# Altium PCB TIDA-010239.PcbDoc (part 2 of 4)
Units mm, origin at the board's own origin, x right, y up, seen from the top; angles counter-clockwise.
Board outline 160 x 175 mm, 4 copper layers (Top Layer, Inside 1, Inside 2, Bottom Layer), stack 1.787 mm thick; 299 components, 146 nets, 710 pads, 164 vias.
Unrouted connection lines stored in the file: 9.
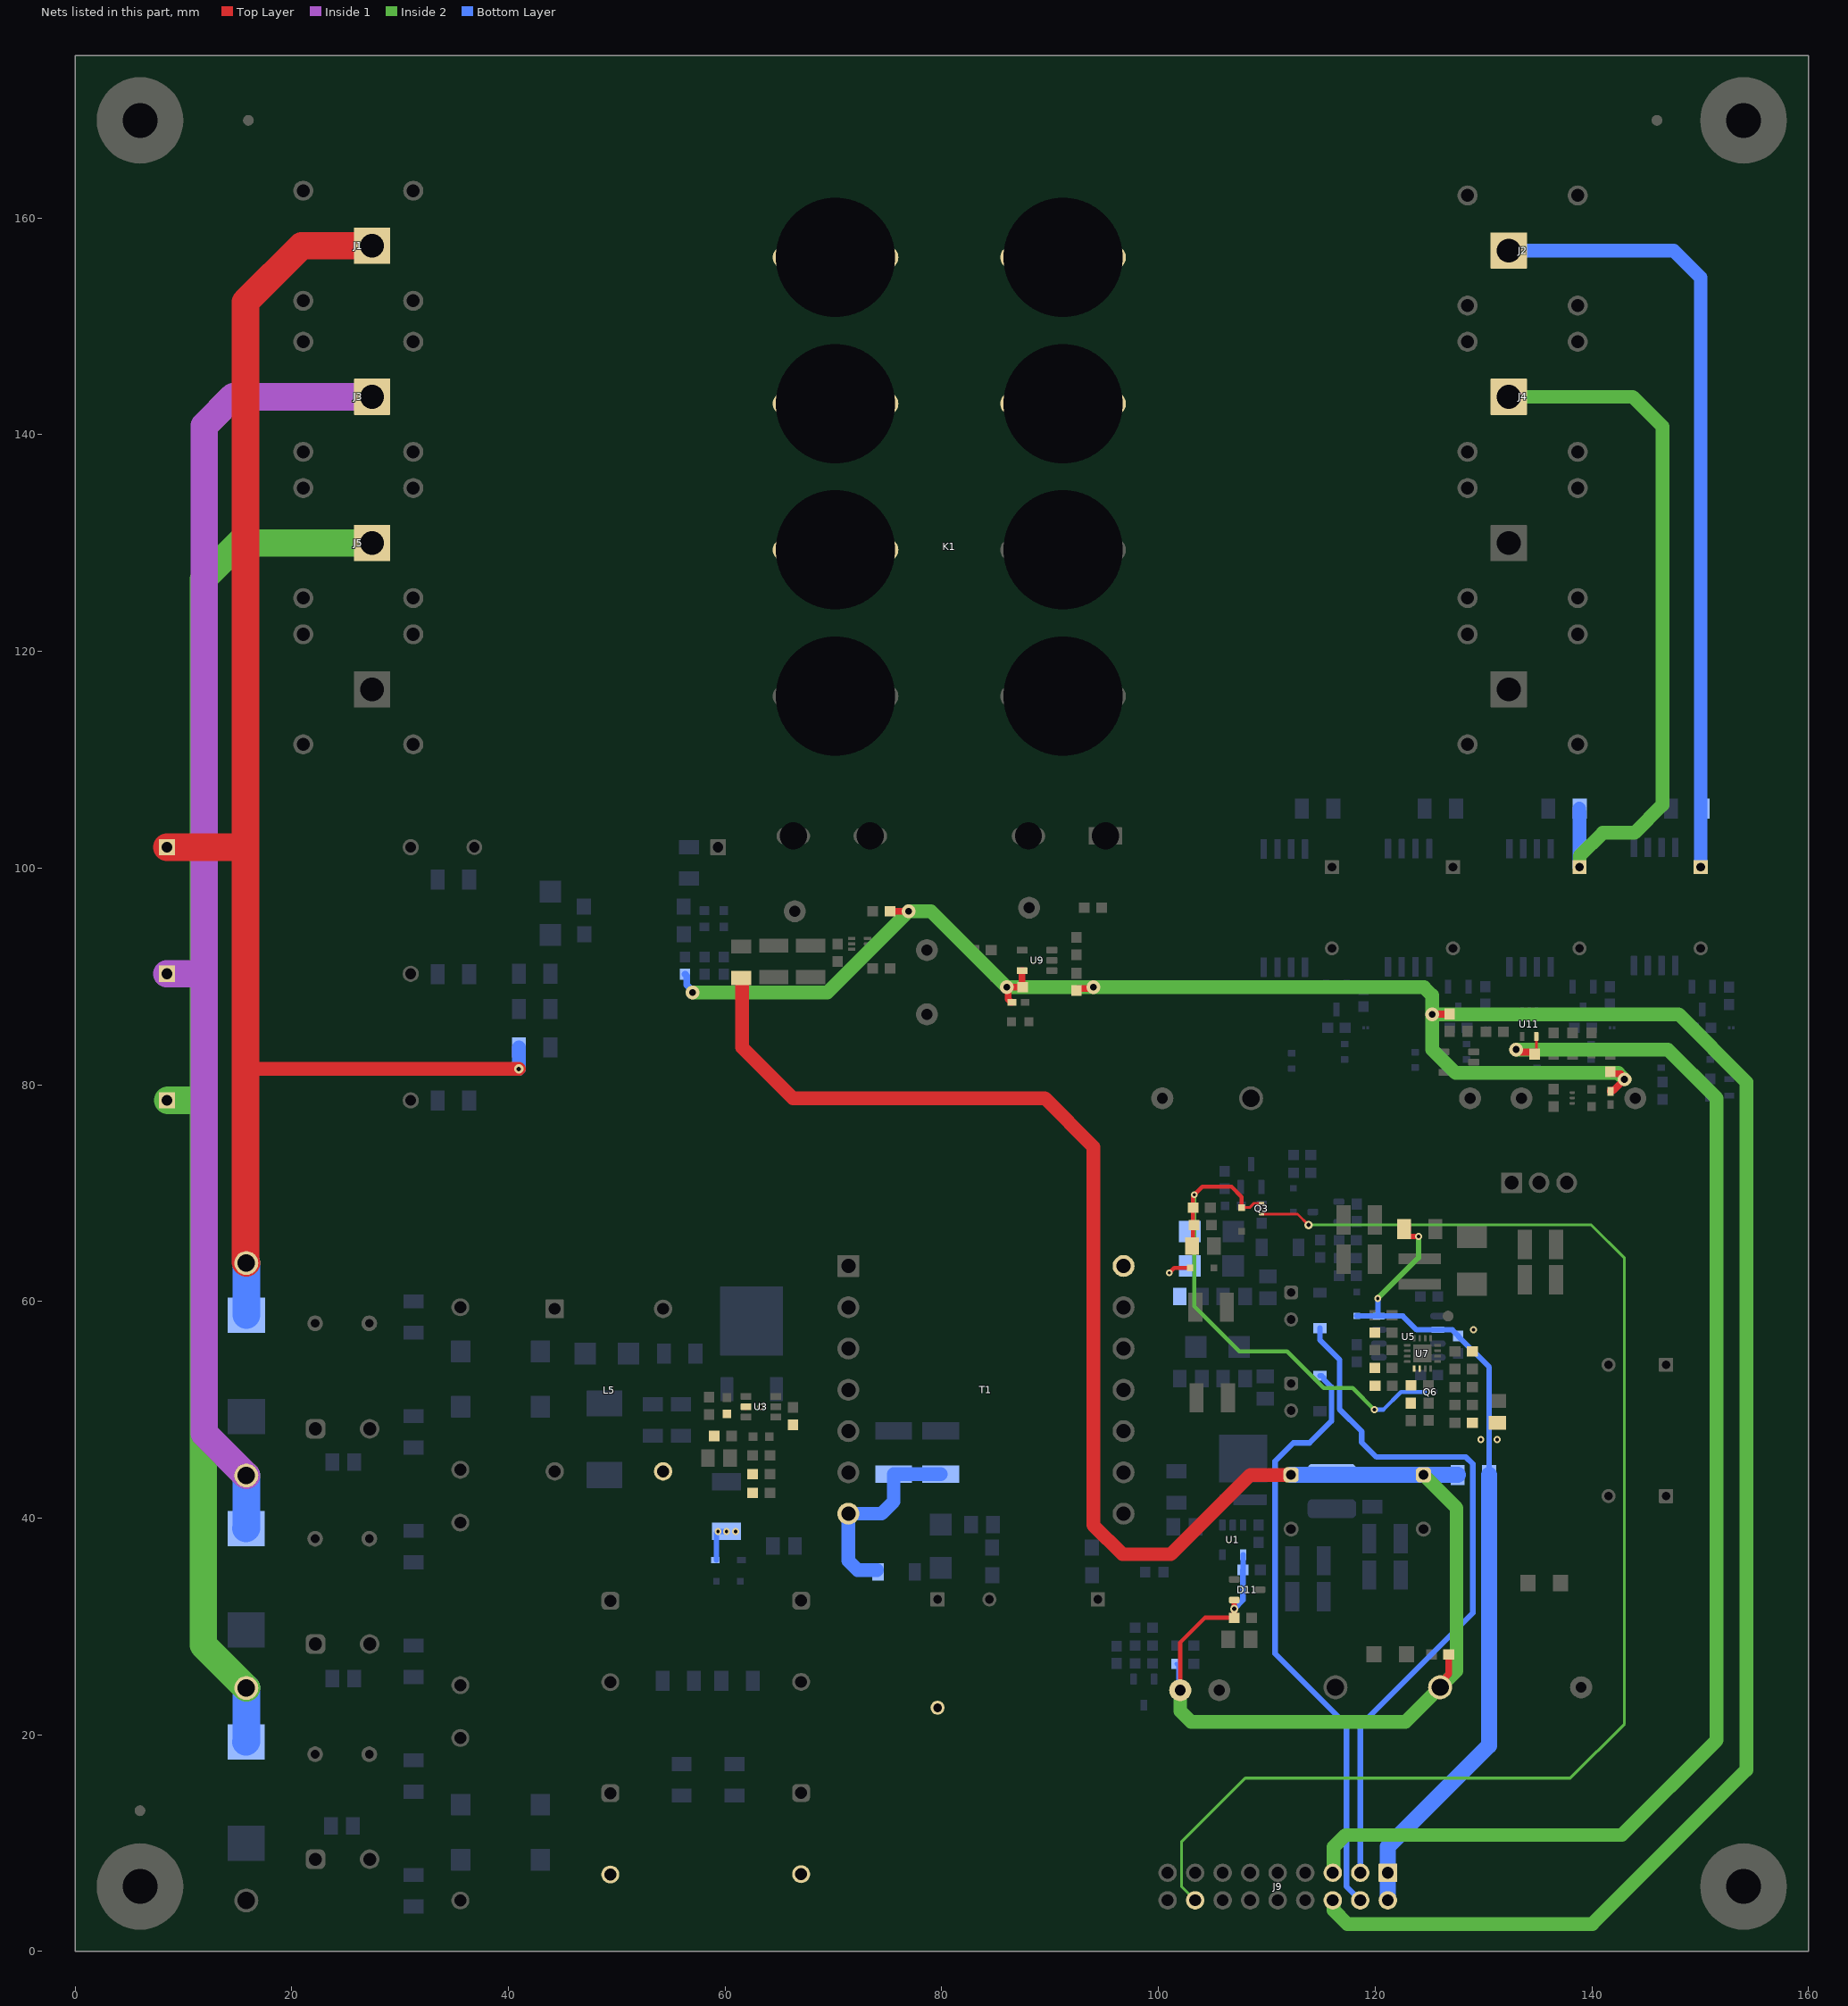
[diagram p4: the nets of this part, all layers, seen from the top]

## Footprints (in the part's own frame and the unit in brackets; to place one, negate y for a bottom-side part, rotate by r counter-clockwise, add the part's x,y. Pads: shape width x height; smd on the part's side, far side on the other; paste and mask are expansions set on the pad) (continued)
WCAP-ATUL_D10H20 [mm] "Aluminum Electrolytic Capacitors, 10x20mm"
  rrect50% 1.4x1.4 hole 0.9: 1(2.5,0)
  round 1.4 hole 0.9: 2(-2.5,0)
  silkscreen extent -5.25,-5.25 5.25,5.25, body extent -4.99,-5 5,5, height 20.31
WCAP-CSGP_0603_L1.6W0.8H0.8_Reflow [mm] "Ceramic Capacitors, body 1.6x0.8mm"
  rect 0.8x0.8 smd: 1(-0.75,0) 2(0.75,0)
  body extent -0.8,-0.4 0.8,0.4, height 0.8
WCAP-FTBE_L18W8.5H15 [mm] "THT Film Capacitors, body 18x8.5mm"
  round 1.65 hole 1.1: 1(-7.5,0) 2(7.5,0)
  silkscreen extent -9.75,-4.75 9.75,4.75, body extent -9,-4.25 9,4.25, height 15.05
WE-PD2-S [mm] "WURTH"
  rrect50% 1.75x4.5 smd: 1(-1.625,0) 2(1.625,0)
  Top Layer region: -1.375,2.25 -0.75,2.25 -0.75,-2.25 -1.375,-2.25
  Top Layer region: 1.375,-2.25 0.75,-2.25 0.75,2.25 1.375,2.25
  silkscreen extent -0.4,-2.1 0.4,2.12, body extent -2.24,-2 2.24,2, height 3.18
WE-TI_1014 [mm] "Radial Leaded Wire Wound Inductor, body diameter 10.5mm"
  rrect50% 1.8x1.8 hole 1.2: 1(-2.5,0)
  round 1.8 hole 1.2: 2(2.5,0)
  silkscreen extent -5.87,-5.25 5.25,5.25, body extent -5,-5 5,5, height 14.1
WEEE_Minimum [mm] "WEEElie bin"
  silkscreen extent -2.42,-4.38 2.52,2.65
WL-SMCW_GREEN [mm] "WURTH"
  rect 0.8x0.8 smd: 1(-0.8,0) 2(0.8,0)
  silkscreen extent -1.9,-0.8 1.2,0.8, body extent -0.85,-0.45 0.85,0.45, height 0.8
WL_SMCW_RED_1206 [mm] "SMD, 2-Leads, Body 3.2x1.6mm, Pitch 3mm"
  rect 1.4x1.5 smd: 1(-1.5,0) 2(1.5,0)
  silkscreen extent -2.9,-1.1 2.2,1.1, body extent -1.6,-0.85 1.6,0.85, height 0.78
X3-DFN0603-2 [mm] "SMD, 2-Leads, Body 0.62x0.32mm"
  rect 0.23x0.3 smd mask+0.102: 1(-0.19,0) 2(0.19,0)
  silkscreen extent -0.69,-0.48 0.32,0.48, body extent -0.32,-0.17 0.32,0.17, height 0.35
XEL4030_310 [mm] "SMD, 2-Leads, Body 4x4mm, Pitch 2.37mm"
  rect 0.98x3.9 smd: 1(-1.185,0) 2(1.185,0)
  silkscreen extent -2.3,-2.3 2.3,2.3, body extent -2.15,-2.15 2.15,2.15, height 3.1
YJK0003A#1 [mm] "SMD, 3-Leads, Body 1.49x0.73mm"
  rrect50% 0.2x0.39 on Top Paste: 1(-0.525,0) 2(0,0) 3(0.525,0)
  rrect80% 0.25x0.49 smd paste-0.15 mask-0.05: 1(-0.5,0) 2(0,0) 3(0.5,0)
  silkscreen extent -0.9,-0.5 0.9,0.5, body extent -0.75,-0.37 0.74,0.36, height 0.35
YJK0003A#2 [mm] "SMD, 3-Leads, Body 1.49x0.73mm"
  rrect50% 0.2x0.39 on Bottom Paste: 1(-0.525,0) 2(0,0) 3(0.525,0)
  rrect80% 0.25x0.49 smd paste-0.15 mask-0.05: 1(-0.5,0) 2(0,0) 3(0.5,0)
  silkscreen extent -0.9,-0.5 0.9,0.5, body extent -0.75,-0.37 0.74,0.36, height 0.35

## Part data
C1 C11: library part CMP-0008246-2, "CAP, CERM, 68 pF, 250 V, +/- 5%, C0G/NP0, 0805", Cap_Case=0805, Manufacturer=MuRata, Supplier Part Number 1=490-5540-1-ND, TempCo=C0G/NP0, Tolerance_%=5%, Value1=Unknown, Value2=250V, ValueDisplayed=68pF
C2 C3: library part CMP-0127096-1, "Cap Ceramic Disc 3300pF 20% 300VAC Thru-Hole 10.0x5.0x10.0 Ammo pack", Manufacturer=Murata, Operating Temperature Range="-40°C to +125°C", TempCo=+20/-55%, Temperature Characteristic=E, Tolerance_%=20%, ValueDisplayed=3300pF, Voltage Ac Rating X=440V, Voltage Ac Rating Y=300V
C4 C12: library part CMP-0116473-1, "WCAP-ATG8 Aluminum Electrolytic Capacitor, Radial, THT, D6.3 x H11mm, 100uF, 25V", Capacitance Tolerance=+/-20%, Leakage Current=25uA, Manufacturer="Wurth Elektronik", Operating Temperature Max=85°C, Operating Temperature Min=-40°C, Rated Voltage (DC)=25V, Ripple Current=209mA
C5 C10 C21 C22 C23 C24 C45 C46 C48 C49 C58 C59: library part CMP-0082267-1, "CAP, CERM, 22 µF, 25 V,+/- 10%, X7R, 1210", Cap_Case=1210, Manufacturer=Yageo, Supplier Part Number 1=311-2032-2-ND, TempCo=X7R, Tolerance_%=10%, Value1="0.001 ohm", Value2=25V, ValueDisplayed=22µF
C6 C7: library part CMP-0009326-2, "CAP, CERM, 0.1 uF, 1000 V, +/- 10%, X7R, 1812", Cap_Case=1812, Manufacturer=Kemet, Supplier Part Number 1=399-6523-1-ND, TempCo=X7R, Tolerance_%=10%, Value1=Unknown, Value2=1000V, ValueDisplayed=0.1uF
C8: library part CMP-0009039-2, "CAP, CERM, 1000 pF, 500 V, +/- 10%, X7R, 1206", Cap_Case=1206, Manufacturer=Vishay-Vitramon, Supplier Part Number 1=720-1019-1-ND, TempCo=X7R, Tolerance_%=10%, Value1=Unknown, Value2=500V, ValueDisplayed=1000pF
C9 C15 C20: library part CMP-0105615-1, "WCAP-FTBE Film Capacitor, THT, L18 x W8.5 x H15mm, 100nF, 1000V", Capacitance Tolerance=+/-10%, Insulation Resistance=9000MOhm, Manufacturer="Wurth Elektronik", Operating Temperature Max=85°C, Operating Temperature Min=-40°C, Rate of Voltage Rise=44V/us, Rated Voltage (DC)=1000V
C13 C14 C16 C17: library part CMP-0102466-1, "WCAP-ATG5 Aluminum Electrolytic Capacitor, Radial, THT, D16 x H25mm, 68µF, 400V", Capacitance Tolerance=+/-20%, Leakage Current=816uA, Manufacturer="Wurth Elektronik", Operating Temperature Max=105°C, Operating Temperature Min=-25°C, Rated Voltage (DC)=400V, Ripple Current=410mA
C18 C29 C32 C39 C41 C43 C44 C47 C52 C60 C61 C64 C67 C73: library part CMP-0007044-5, "CAP, CERM, 0.1 uF, 50 V, +/- 10%, X7R, 0603", Cap_Case=0603, Manufacturer=TDK, Supplier Part Number 1=445-1314-1-ND, TempCo=X7R, Tolerance_%=10%, Value1="0.0296 ohm", Value2=50V, ValueDisplayed=0.1uF
C19: library part CMP-0007499-4, "CAP, CERM, 2.2 uF, 16 V, +/- 10%, X7R, 0603", Cap_Case=0603, Manufacturer=MuRata, Supplier Part Number 1=81-GRM188Z71C225KE3D, TempCo=X7R, Tolerance_%=10%, Value1=Unknown, Value2=16V, ValueDisplayed=2.2uF
C25 C26: library part CMP-0116844-1, "WCAP-ATUL Aluminum Electrolytic Capacitor, Radial, THT, D10 x H20mm, 680µF, 25V", Capacitance Tolerance=20%, Leakage Current=170uA, Manufacturer="Wurth Elektronik", Operating Temperature Max=105°C, Operating Temperature Min=-40°C, Rated Voltage (DC)=25V, Ripple Current=1400mA
C27: library part CMP-0008236-2, "CAP, CERM, 100 pF, 250 V, +/- 5%, C0G/NP0, 0805", Cap_Case=0805, Manufacturer=MuRata, Supplier Part Number 1=490-5542-1-ND, TempCo=C0G/NP0, Tolerance_%=5%, Value1=Unknown, Value2=250V, ValueDisplayed=100pF
C28: library part CMP-0006897-4, "CAP, CERM, 2200 pF, 50 V, +/- 10%, X7R, 0603", Cap_Case=0603, Manufacturer=Kemet, Supplier Part Number 1=1362428, TempCo=X7R, Tolerance_%=10%, Value1=Unknown, Value2=50V, ValueDisplayed=2200pF
C30 C37: library part CMP-0008802-2, "CAP, CERM, 10 uF, 50 V, +/- 10%, X7R, 1206", Cap_Case=1206, Manufacturer=Samsung, Supplier Part Number 1=1276-6767-1-ND, TempCo=X7R, Tolerance_%=10%, Value1=Unknown, Value2=50V, ValueDisplayed=10uF
C31: library part CMP-0007870-2, "CAP, CERM, 4.7 uF, 25 V, +/- 10%, X7R, 0805", Cap_Case=0805, Manufacturer=TDK, Supplier Part Number 1=445-5972-1-ND, TempCo=X7R, Tolerance_%=10%, Value1=Unknown, Value2=25V, ValueDisplayed=4.7uF
C33 C38: library part CMP-0118889-1, "WCAP-CSGP Multilayer Ceramic Chip Capacitor, General Purpose, size 0603, NP0, 100pF, 50VDC", Capacitance Tolerance=+/-5%, Insulation Resistance=10GOhm, Manufacturer="Wurth Elektronik", Operating Temperature Max=125°C, Operating Temperature Min=-55°C, Rated Voltage (DC)=50V
C34: library part CMP-0115476-1, "WCAP-CSGP Multilayer Ceramic Chip Capacitor, General Purpose, size 0603, X7R, 47nF, 50VDC", Capacitance Tolerance=+/-10%, Insulation Resistance=10GOhm, Manufacturer="Wurth Elektronik", Operating Temperature Max=125°C, Operating Temperature Min=-55°C, Rated Voltage (DC)=50V
C35: library part CMP-0006893-4, "CAP, CERM, 220 pF, 50 V, +/- 5%, C0G/NP0, 0603", Cap_Case=0603, Manufacturer=Kemet, Supplier Part Number 1=399-1066-1-ND, TempCo=C0G/NP0, Tolerance_%=5%, Value1=Unknown, Value2=50V, ValueDisplayed=220pF
C36: library part CMP-0006835-4, "CAP, CERM, 4700 pF, 50 V, +/- 10%, X7R, 0603", Cap_Case=0603, Manufacturer="Wurth Elektronik", Supplier Part Number 1=710-885012206087, TempCo=X7R, Tolerance_%=10%, Value1=Unknown, Value2=50V, ValueDisplayed=4700pF
C40 C42: library part CMP-0095175-1, "2.5 F (EDLC) Supercapacitor 3.9 V Radial 80mOhm 5000 Hrs @ 85°C", Digikey Part Number=283-PHVL-3R9V255-R-ND, Manufacturer="Cooper Bussmann", Mouser Part Number=504-PHVL-3R9V255-R, Operating Temperature Range="-40°C to +85°C", Tolerance_%=30%, ValueDisplayed=2.5F
C50: library part CMP-0084374-1, "CAP, CERM, 6.8 pF, 100 V,+/- 3.7%, C0G/NP0, 0603", Cap_Case=0603, Manufacturer=Yageo, TempCo=C0G/NP0, Tolerance_%=3.7%, Value2=100V, ValueDisplayed=6.8pF
C51: library part CMP-0006834-5, "CAP, CERM, 470 pF, 50 V, +/- 10%, X7R, 0603", Cap_Case=0603, Manufacturer="Wurth Elektronik", Supplier Part Number 1=710-885012206081, TempCo=X7R, Tolerance_%=10%, Value1=Unknown, Value2=50V, ValueDisplayed=470pF
C53: library part CMP-0006854-4, "CAP, CERM, 0.01 uF, 50 V, +/- 10%, X7R, 0603", Cap_Case=0603, Manufacturer=Kemet, Supplier Part Number 1=399-1091-1-ND, TempCo=X7R, Tolerance_%=10%, Value1=Unknown, Value2=50V, ValueDisplayed=0.01uF
C54 C55 C56: library part CMP-0012419-3, "CAP, Film, 1 uF, 630 V, +/- 20%, 0.018 ohm, TH", Manufacturer=TDK, Supplier Part Number 1=495-2324-ND, Tolerance_%=20%, Value1="0.018 ohm", Value2=630V, ValueDisplayed=1uF
C57: library part CMP-0040174-1, "Cap Film Suppression Y2 0.1uF 1250VDC/300VAC PP 20% (26 X 10.5 X 19mm) Radial 22.5mm 110C Tray", Digikey Part Number=399-5422-ND, Manufacturer=Kemet, Mouser Part Number=80-PHE850ED6100MD18, Operating Temperature Range="-55°C to +110°C", Tolerance_%=20%, ValueDisplayed=0.1uF, Voltage Ac Rating Y=300V
C62 C65 C69 C71: library part CMP-0120129-1, "1000 pF ±20% 440VAC Ceramic Capacitor Y5U (E) Radial, Disc", Digikey Part Number=BC5267CT-ND, Manufacturer=Vishay, Mouser Part Number=72-VY2102M29Y5US6TV7, Operating Temperature Range="-40°C to +125°C", TempCo=+22/-56%, Temperature Characteristic=Y5U, Tolerance_%=20%, ValueDisplayed=1000pF, Voltage Ac Rating X=440V, Voltage Ac Rating Y=300V
C63 C68 C70 C72: library part CMP-0085572-1, "CAP, CERM, 47 pF, 100 V,+/- 5%, C0G/NP0, AEC-Q200 Grade 1, 0603", Cap_Case=0603, Manufacturer=Kemet, TempCo=C0G/NP0, Tolerance_%=5%, Value2=100V, ValueDisplayed=47pF
C66: library part CMP-0006751-4, "CAP, CERM, 100 pF, 25 V, +/- 10%, X7R, 0603", Cap_Case=0603, Manufacturer=AVX, Supplier Part Number 1=55J3899, TempCo=X7R, Tolerance_%=10%, Value1=Unknown, Value2=25V, ValueDisplayed=100pF
C74: library part CMP-0007139-4, "CAP, CERM, 1 uF, 25 V, +/- 10%, X7R, AEC-Q200 Grade 1, 0603", Cap_Case=0603, Manufacturer=MuRata, Supplier Part Number 1=490-10673-1-ND, TempCo=X7R, Tolerance_%=10%, Value1=Unknown, Value2=25V, ValueDisplayed=1uF
C75: library part CMP-0008918-2, "CAP, CERM, 2200 pF, 1000 V, +/- 10%, X7R, 1206", Cap_Case=1206, Manufacturer=MuRata, Supplier Part Number 1=490-3496-1-ND, TempCo=X7R, Tolerance_%=10%, Value1=Unknown, Value2=1000V, ValueDisplayed=2200pF
C76: library part CMP-0108297-1, "WCAP-CSGP Multilayer Ceramic Chip Capacitor, General Purpose, size 0603, X7R, 1nF, 50VDC", Capacitance Tolerance=+/-10%, Insulation Resistance=10GOhm, Manufacturer="Wurth Elektronik", Operating Temperature Max=125°C, Operating Temperature Min=-55°C, Rated Voltage (DC)=50V
C77: library part CMP-0091480-1, "0603 0.22 uF 16 V ±10 % Tolerance X7R SMT Multilayer Ceramic Capacitor", Digikey Part Number=311-1426-1-ND, Manufacturer=Yageo, Mouser Part Number=603-CC603KRX7R7BB224, Operating Temperature Range="-55°C to +125°C", TempCo=15%, Temperature Characteristic=X7R, Tolerance_%=10%, ValueDisplayed=220nF, Voltage=16V
D1 D5 D16: library part CMP-0028981-2, "Diode, Schottky, 200 V, 1 A, SMA", Manufacturer="Micro Commercial Components", Value1=1A, Value2=0.92V
D2 D6: library part CMP-0028526-2, "Diode, Schottky, 40 V, 0.5 A, SOD-123", Manufacturer="ON Semiconductor", Value1=0.5A, Value2=0.51V
D3 D8: library part CMP-0029252-3, "Diode, Switching-Bridge, 1000 V, 2.2 A, 8.25x6.6mm", Manufacturer="Micro Commercial Components", Value1=2.2A, Value2=1.1V
D4: library part CMP-0127069-1, "209V Clamp 7.2A Ipp Tvs Diode Surface Mount DO-214AB (SMCJ)", Breakdown Voltage=144V, Clamping Voltage=209V, Digikey Part Number=SMCJ130ALFCT-ND, Manufacturer="Littelfuse Inc", Mouser Part Number=576-SMCJ130A, Operating Temperature Range="-65°C to +150°C"
D7 D35: library part CMP-0076882-2, "Diode, Ultrafast, 1000 V, 1 A, SMA", Manufacturer="Diodes Inc.", Value1=1A, Value2=1.7V
D9 D19: library part CMP-0002935-3, "LED, Red, SMD", Color=Red, Manufacturer="Wurth Elektronik", Power_TotalModule=72mW, Value1=0.072W, Value2=2V
D10: library part CMP-0077026-2, "Diode, Ultrafast, 400 V, 1 A, SMA", Manufacturer="Diodes Inc.", Value1=1A, Value2=1.3V
D11: library part CMP-0028613-2, "Diode, Schottky, 30 V, 0.2 A, SOT-23", Manufacturer="ON Semiconductor", Value1=0.2A, Value2=0.8V
D12 D14 D17 D18: library part CMP-0029150-2, "Diode, Switching, 200 V, 0.2 A, AEC-Q101, SOD-323", Manufacturer="ON Semiconductor", Value1=0.2A, Value2=1.25V
D13: library part CMP-0124335-1, "Diode Zener Single 43V ±5% 200mW 2-Pin SOD-323 T/R", Digikey Part Number=112-BZX384C43-E3-08CT-ND, Manufacturer=Vishay, Max Reverse Leakage Current=0.05uA, Mouser Part Number=78-BZX384C43-E3-08, Operating Temperature Range="-55°C to +150°C", Power_W=200mW
D15: library part CMP-0085763-1, "Diode, Zener, 16 V, 300 mW, AEC-Q101, SOD-323", Manufacturer="ON Semiconductor", Power_W=300mW, Value1=0.3W
D20: library part CMP-0028529-2, "Diode, Schottky, 40 V, 2 A, SMB", Manufacturer="ON Semiconductor", Value1=2A, Value2=0.43V
D21 D36: library part CMP-0002905-2, "LED, Green, SMD", Color=Green, Manufacturer="Wurth Elektronik", Value1=W, Value2=3.2V
D22 D24 D25 D27 D29 D31 D32 D33 D34: library part CMP-0120115-1, "Diode 30 V 30mA Surface Mount SOD-523", Digikey Part Number=4786-GSRB751S-40CT-ND, Forward Current=30mA, Manufacturer=Good-Ark, Max Surge Forward Current=200mA, Operating Temperature Range="to +125°C", Peak Reverse Current=0.5uA, ValueDisplayed=2pF
D23 D26 D28 D30: library part CMP-0006072-3, "Diode, Zener, 5.1 V, 250 mW, 2-XFDFN", Manufacturer="Diodes Inc.", Power_W=250mW, Value1=0.25W
F1 F2 F3: library part CMP-0003467-2, "Fuse, 1 A, 250VAC/VDC, SMD", Irating_A=1A, Manufacturer=Littelfuse, Supplier Part Number 1=F2906CT-ND
F4: library part CMP-0003461-2, "Fuse, 1.5 A, 50VAC/VDC, SMD", Irating_A=1.5A, Manufacturer=Littelfuse, Supplier Part Number 1=F1611TR-ND
FID1 FID2 FID3: library part CMP-0077181-1, "Fiducial mark.  There is nothing to buy or mount.", Manufacturer=N/A
H1 H2 H3 H4: library part CMP-0003617-1, "Machine Screw, Round, #4-40 x 1/4, Nylon, Philips panhead", Manufacturer="B&F Fastener Supply", Supplier Part Number 1=H542-ND
J1 J2 J3 J4 J5 J6: library part CMP-0098296-2, "Banana Test Connector, Socket, PCB Mount, 24 A, 1 kV, Gold Plated Contacts, Brown", Current_A=24A, Digikey Part Number=4654-FCR7350N-ND, Manufacturer="CLIFF Electronic Components", Operating Temperature Range="-40°C to +80°C", Voltage_V=1kV
J7 J8: library part CMP-0098294-2, "Banana Test Connector, Socket, PCB Mount, 24 A, 1 kV, Gold Plated Contacts, Green", Current_A=24A, Digikey Part Number=4654-FCR7350G-ND, Manufacturer="CLIFF Electronic Components", Operating Temperature Range="-40°C to +80°C", Voltage_V=1kV
J9: library part CMP-0124771-1, "Connector Header Through Hole 18 position 0.100\" (2.54mm)", Current_A=3A, Digikey Part Number=732-5300-ND, Manufacturer=Wurth, Mouser Part Number=710-61301821121, Operating Temperature Range="-40°C to +105°C", Voltage_V=250V
K1: library part CMP-0127083-1, "General Purpose Relay 5PST-4NO/1NC (4 Form A, 1 Form B) 12VDC Coil Through Hole", Coil Current_A=417mA, Coil Power_W=5W, Coil Resistance=28.8Ω, Coil Voltage_VDC=12V, Contact Rating_A=40A, Digikey Part Number=39-G9KC-4A1BDC12-ND, Manufacturer=Omron, Mouser Part Number=653-G9KC-4A1B-DC12, Operating Temperature Range="-40°C to +85°C"
L1 L3: library part CMP-0003090-1, "Ferrite Bead, 1000 ohm @ 100 MHz, 0.2 A, 0805", Manufacturer="Wurth Elektronik", Supplier Part Number 1=732-1606-1-ND, Value1="0.45 ohm", Value2=0.2A, ValueDisplayed="1000 ohm"
L2 L4 L6: library part CMP-0099585-1, "WE-TI Radial Leaded Wire Wound Inductor, size 1014, 150uH, 2A, 0.18Ohm", DC Resistance=0.16Ohm, DC Resistance Max=0.18Ohm, Manufacturer="Wurth Elektronik", Operating Temperature Max=125°C, Operating Temperature Min=-40°C, Rated Current=2A, Saturation Current=2.1A, Self Resonant Frequency=3.1MHz
L5: library part CMP-0124348-1, "6.8 mH @ 10 kHz 2 Line Common Mode Choke Through Hole 1A DCR 300mOhm", Digikey Part Number=732-4571-ND, Manufacturer="Wurth Electronics", Mouser Part Number=710-7446121007, Operating Temperature Range="-40°C to +125°C", Test Frequency=10kHz, Tolerance_%=30%
L7: library part CMP-0064228-1, "Inductor, Shielded Drum Core, Ferrite, 1 uH, 4 A, 0.049 ohm, SMD", Manufacturer="Wurth Elektronik", Supplier Part Number 1=732-1249-1-ND, Value1="0.049 ohm", Value2=4A, ValueDisplayed=1uH
L8: library part CMP-0061090-1, "Inductor, Shielded, 3.3 uH, 5 A, 0.0286 ohm, SMD", Manufacturer=Coilcraft, Value1="0.0286 ohm", Value2=5A, ValueDisplayed=3.3uH
L9: library part CMP-0003140-1, "Ferrite Bead, 280 ohm @ 100 MHz, 3.5 A, 1206", Manufacturer="Wurth Elektronik", Supplier Part Number 1=732-6132-1-ND, Value1="0.022 ohm", Value2=3.5A, ValueDisplayed="280 ohm"
LBL1: library part CMP-0003625-1, "Thermal Transfer Printable Labels, 0.650\" W x 0.200\" H - 10,000 per roll", Manufacturer=Brady, Supplier Part Number 1=97C5133
Logo1: library part CMP-0074844-2, Manufacturer="Texas Instruments"
Logo2: library part CMP-0074838-1, "Texas Instrument Corporate Signature"
Logo3: library part CMP-0074847-1, "FCC_disclaimer"
Logo4: library part CMP-0074769-4, Manufacturer="Texas Instruments"
LOGO5 LOGO6 LOGO7 LOGO8 LOGO9: library part CMP-0074835-1, "IEC 61010-1 High Voltage Warning"
NT1: library part CMP-0078142-6, "Single point connection between nets.", Manufacturer=N/A
Q1: library part CMP-0089849-1, "Mosfet, N-Ch, 200V, 24A, 150Deg C Rohs Compliant: Yes", Digikey Part Number=BSC500N20NS3GATMA1CT-ND, Drain To Source Breakdown Voltage=200V, Input Capacitace At Vds="2770pF @ 100V", Manufacturer=Infineon, Operating Temperature Range="-55°C to +175°C", Pulse Drain Current=97A, Typ Forward Diode Voltage=1V
Q2: library part CMP-0091039-1, "Trans MOSFET N-CH 950V 4A 3-Pin(2+Tab) DPAK T/R", Digikey Part Number=IPD95R2K0P7ATMA1CT-ND, Drain To Source Breakdown Voltage=950V, Input Capacitace At Vds="330pF @ 400V", Manufacturer="Infineon Technologies", Mouser Part Number=726-IPD95R2K0P7ATMA1, Operating Temperature Range="-55°C to +150°C", Power_W=37W, Pulse Drain Current=10A, Typ Forward Diode Voltage=0.9V
Q3 Q6 Q7 Q8: library part CMP-0067551-1, "MOSFET, N-CH, 30 V, 5.9 A, YJK0003A (PICOSTAR-3)", Alternate Manufacturer=None, Manufacturer="Texas Instruments", Supplier Part Number 1=296-45068-1-ND, Value1="0.033 ohm", Value2="1.9 nC"
Q4: library part CMP-0124068-1, "N-Channel 60 V 14A (Tc) 37W (Tc) Through Hole TO-220-3", Digikey Part Number=IRFIZ24GPBF-ND, Drain To Source Breakdown Voltage=60V, Input Capacitance At Vds="640pF @ 25V", Manufacturer=Vishay, Mouser Part Number=844-IRFIZ24GPBF, Operating Temperature Range="-55°C to +175°C", Power_W=37W, Pulse Drain Current=56A
Q5: library part CMP-0000419-2, "Transistor, NPN, 40 V, 0.2 A, SOT-23", Manufacturer="ON Semiconductor", Supplier Part Number 1=MMBT3904LT1GOSCT-ND, Value1="0.2 A", Value2=300
R1 R6: library part CMP-0020619-3, "RES, 1.0 k, 5%, 0.125 W, AEC-Q200 Grade 0, 0805", Manufacturer=Panasonic, Power_W=125mW, Supplier Part Number 1=P1.0KACT-ND, TempCo="200 ppm/C", Tolerance_%=5%, Value2=0.125W, Value_Code=1k00, ValueDisplayed=1.0k
R2 R4 R7 R9 R12 R16 R19: library part CMP-0018684-3, "RES, 470 k, 5%, 0.25 W, AEC-Q200 Grade 0, 1206", Manufacturer=Vishay-Dale, Power_W=250mW, Supplier Part Number 1=541-470KECT-ND, TempCo="200 ppm/C", Tolerance_%=5%, Value2=0.25W, Value_Code=470k
R3 R10 R15: library part CMP-0020842-3, "RES, 10.0 k, 1%, 0.125 W, AEC-Q200 Grade 0, 0805", Manufacturer=Vishay-Dale, Power_W=125mW, Supplier Part Number 1=541-10.0KCCT-ND, TempCo="100 ppm/C", Tolerance_%=1%, Value2=0.125W, Value_Code=10k0, ValueDisplayed=10.0k
R5 R8 R13 R17: library part CMP-0018610-3, "RES, 1.0 M, 5%, 0.25 W, AEC-Q200 Grade 0, 1206", Manufacturer=Vishay-Dale, Power_W=250mW, Supplier Part Number 1=541-1.0MECT-ND, TempCo="200 ppm/C", Tolerance_%=5%, Value2=0.25W, Value_Code=1M00, ValueDisplayed=1.0M
R11: library part CMP-0018578-3, "RES, 10, 5%, 0.25 W, AEC-Q200 Grade 0, 1206", Manufacturer=Vishay-Dale, Power_W=250mW, Supplier Part Number 1=541-10ECT-ND, TempCo="200 ppm/C", Tolerance_%=5%, Value2=0.25W, Value_Code=10R0, ValueDisplayed=10
R14 R18 R59 R60 R61 R62 R87 R88 R89 R90: library part CMP-0018759-2, "RES, 0, 5%, 0.25 W, 1206", Manufacturer="Yageo America", Power_W=250mW, Supplier Part Number 1=311-0.0ERCT-ND, TempCo="200 ppm/C", Tolerance_%=5%, Value2=0.25W, Value_Code=0000, ValueDisplayed=0
R20 R37 R41 R48: library part CMP-0023153-5, "RES, 4.70 k, 1%, 0.1 W, 0603", Manufacturer=Yageo, Power_W=100mW, Supplier Part Number 1=311-4.70KHRCT-ND, TempCo="100 ppm/C", Tolerance_%=1%, Value2=0.1W, Value_Code=4k70, ValueDisplayed=4.70k
R21: library part CMP-0020835-3, "RES, 100, 1%, 0.125 W, AEC-Q200 Grade 0, 0805", Manufacturer=Vishay-Dale, Power_W=125mW, Supplier Part Number 1=541-100CCT-ND, TempCo="100 ppm/C", Tolerance_%=1%, Value2=0.125W, Value_Code=100R, ValueDisplayed=100
R22: library part CMP-0022448-4, "RES, 49.9, 1%, 0.1 W, AEC-Q200 Grade 0, 0603", Manufacturer=Vishay-Dale, Power_W=100mW, Supplier Part Number 1=541-49.9HCT-ND, TempCo="100 ppm/C", Tolerance_%=1%, Value2=0.1W, Value_Code=49R9, ValueDisplayed=49.9
R23: library part CMP-0018603-3, "RES, 1.0 k, 5%, 0.25 W, AEC-Q200 Grade 0, 1206", Manufacturer=Vishay-Dale, Power_W=250mW, Supplier Part Number 1=541-1.0KECT-ND, TempCo="200 ppm/C", Tolerance_%=5%, Value2=0.25W, Value_Code=1k00, ValueDisplayed=1.0k
R24: library part CMP-0020497-3, "RES, 20, 5%, 0.125 W, AEC-Q200 Grade 0, 0805", Manufacturer=Vishay-Dale, Power_W=125mW, Supplier Part Number 1=541-20ACT-ND, TempCo="200 ppm/C", Tolerance_%=5%, Value2=0.125W, Value_Code=20R0, ValueDisplayed=20
R25: library part CMP-0022277-4, "RES, 2.49 k, 1%, 0.1 W, AEC-Q200 Grade 0, 0603", Manufacturer=Vishay-Dale, Power_W=100mW, Supplier Part Number 1=541-2.49KHCT-ND, TempCo="100 ppm/C", Tolerance_%=1%, Value2=0.1W, Value_Code=2k49, ValueDisplayed=2.49k
R26: library part CMP-0022563-4, "RES, 6.81 k, 1%, 0.1 W, AEC-Q200 Grade 0, 0603", Manufacturer=Vishay-Dale, Power_W=100mW, Supplier Part Number 1=541-6.81KHCT-ND, TempCo="100 ppm/C", Tolerance_%=1%, Value2=0.1W, Value_Code=6k81, ValueDisplayed=6.81k
R27 R29: library part CMP-0021759-3, "RES, 60.4 k, 1%, 0.125 W, AEC-Q200 Grade 0, 0805", Manufacturer=Panasonic, Power_W=125mW, Supplier Part Number 1=P60.4KCCT-ND, TempCo="100 ppm/C", Tolerance_%=1%, Value2=0.125W, Value_Code=60k4, ValueDisplayed=60.4k
R28: library part CMP-0023066-5, "RES, 38.3 k, 1%, 0.1 W, 0603", Manufacturer=Yageo, Power_W=100mW, Supplier Part Number 1=311-38.3KHRCT-ND, TempCo="100 ppm/C", Tolerance_%=1%, Value2=0.1W, Value_Code=38k3, ValueDisplayed=38.3k
R30 R33 R40 R43 R44 R50 R56 R58 R66 R68 R69 R72 R77 R80 R92: library part CMP-0022746-5, "RES, 10.0 k, 1%, 0.1 W, 0603", Manufacturer=Yageo, Power_W=100mW, Supplier Part Number 1=311-10.0KHRCT-ND, TempCo="100 ppm/C", Tolerance_%=1%, Value2=0.1W, Value_Code=10k0, ValueDisplayed=10.0k
R31 R38 R51: library part CMP-0021990-4, "RES, 100 k, 1%, 0.1 W, AEC-Q200 Grade 0, 0603", Manufacturer=Vishay-Dale, Power_W=100mW, Supplier Part Number 1=541-100KHCT-ND, TempCo="100 ppm/C", Tolerance_%=1%, Value2=0.1W, Value_Code=100k
R32: library part CMP-0023036-5, "RES, 33.2 k, 1%, 0.1 W, 0603", Manufacturer=Yageo, Power_W=100mW, Supplier Part Number 1=311-33.2KHRCT-ND, TempCo="100 ppm/C", Tolerance_%=1%, Value2=0.1W, Value_Code=33k2, ValueDisplayed=33.2k
R34 R46 R47 R81: library part CMP-0022109-5, "RES, 1.00 k, 1%, 0.1 W, AEC-Q200 Grade 0, 0603", Manufacturer=Vishay-Dale, Power_W=100mW, Supplier Part Number 1=541-1.00KHCT-ND, TempCo="100 ppm/C", Tolerance_%=1%, Value2=0.1W, Value_Code=1k00, ValueDisplayed=1.00k
R35: library part CMP-0016530-2, "RES, 0.5, 1%, 1 W, 2010", Manufacturer="Stackpole Electronics Inc", Power_W=1W, Supplier Part Number 1=CSRN2010FKR500CT-ND, TempCo="250 ppm/C", Tolerance_%=1%, Value_Code=R500, ValueDisplayed=0.5
R36: library part CMP-0023037-5, "RES, 33.0 k, 1%, 0.1 W, 0603", Manufacturer=Yageo, Power_W=100mW, Supplier Part Number 1=311-33.0KHRCT-ND, TempCo="100 ppm/C", Tolerance_%=1%, Value2=0.1W, Value_Code=33k0, ValueDisplayed=33.0k
R39: library part CMP-0025700-4, "RES, 100, 5%, 0.1 W, AEC-Q200 Grade 0, 0603", Manufacturer=Vishay-Dale, Power_W=100mW, Supplier Part Number 1=541-100GCT-ND, TempCo="200 ppm/C", Tolerance_%=5%, Value2=0.1W, Value_Code=100R, ValueDisplayed=100
R42: library part CMP-0022478-4, "RES, 4.99, 1%, 0.1 W, AEC-Q200 Grade 0, 0603", Manufacturer=Vishay-Dale, Power_W=100mW, Supplier Part Number 1=541-4.99HHCT-ND, TempCo="100 ppm/C", Tolerance_%=1%, Value2=0.1W, Value_Code=4R99, ValueDisplayed=4.99
R45: library part CMP-0022762-5, "RES, 11.8 k, 1%, 0.1 W, 0603", Manufacturer=Yageo, Power_W=100mW, Supplier Part Number 1=311-11.8KHRCT-ND, TempCo="100 ppm/C", Tolerance_%=1%, Value2=0.1W, Value_Code=11k8, ValueDisplayed=11.8k
R49: library part CMP-0021991-4, "RES, 100, 1%, 0.1 W, AEC-Q200 Grade 0, 0603", Manufacturer=Vishay-Dale, Power_W=100mW, Supplier Part Number 1=541-100HCT-ND, TempCo="100 ppm/C", Tolerance_%=1%, Value2=0.1W, Value_Code=100R, ValueDisplayed=100
R52: library part CMP-0023162-4, "RES, 510 k, 1%, 0.1 W, 0603", Manufacturer=Yageo, Power_W=100mW, Supplier Part Number 1=311-510KHRCT-ND, TempCo="100 ppm/C", Tolerance_%=1%, Value2=0.1W, Value_Code=510k
R53: library part CMP-0023133-5, "RES, 47.0 k, 1%, 0.1 W, 0603", Manufacturer=Yageo, Power_W=100mW, Supplier Part Number 1=311-47.0KHRCT-ND, TempCo="100 ppm/C", Tolerance_%=1%, Value2=0.1W, Value_Code=47k0, ValueDisplayed=47.0k
R54: library part CMP-0022996-5, "RES, 2.70 k, 1%, 0.1 W, 0603", Manufacturer=Yageo, Power_W=100mW, Supplier Part Number 1=311-2.70KHRCT-ND, TempCo="100 ppm/C", Tolerance_%=1%, Value2=0.1W, Value_Code=2k70, ValueDisplayed=2.70k
R55: library part CMP-0025309-3, "RES, 46.4 k, 0.5%, 0.1 W, 0603", Manufacturer="Yageo America", Power_W=100mW, TempCo="50 ppm/C", Tolerance_%=0.5%, Value2=0.1W, Value_Code=46k4, ValueDisplayed=46.4k
R57: library part CMP-0023219-5, "RES, 620, 1%, 0.1 W, 0603", Manufacturer=Yageo, Power_W=100mW, Supplier Part Number 1=311-620HRCT-ND, TempCo="100 ppm/C", Tolerance_%=1%, Value2=0.1W, Value_Code=620R, ValueDisplayed=620
R63 R85: library part CMP-0026736-1, "RES, 470, 1%, 0.063 W, 0402", Manufacturer="Yageo America", Power_W=63mW, Supplier Part Number 1=311-470LRCT-ND, TempCo="100 ppm/C", Tolerance_%=1%, Value2=0.063W, Value_Code=470R, ValueDisplayed=470
R64 R67 R70 R71 R74 R86: library part CMP-0081973-1, "RES, 0, 0%, 0.25 W, AEC-Q200 Grade 0, 0603", Manufacturer=Vishay-Dale, Power_W=250mW, Supplier Part Number 1=541-2779-1-ND, Tolerance_%=0%, Value2=0.25W, Value_Code=0
R73 R75 R76: library part CMP-0022899-4, "RES, 1.00 M, 1%, 0.1 W, 0603", Manufacturer=Yageo, Power_W=100mW, Supplier Part Number 1=311-1.00MHRCT-ND, TempCo="100 ppm/C", Tolerance_%=1%, Value2=0.1W, Value_Code=1M00, ValueDisplayed=1.00M
R78: library part CMP-0022809-5, "RES, 150, 1%, 0.1 W, 0603", Manufacturer=Yageo, Power_W=100mW, Supplier Part Number 1=311-150HRCT-ND, TempCo="100 ppm/C", Tolerance_%=1%, Value2=0.1W, Value_Code=150R, ValueDisplayed=150
R79: library part CMP-0022761-5, "RES, 11.5 k, 1%, 0.1 W, 0603", Manufacturer=Yageo, Power_W=100mW, Supplier Part Number 1=311-11.5KHRCT-ND, TempCo="100 ppm/C", Tolerance_%=1%, Value2=0.1W, Value_Code=11k5, ValueDisplayed=11.5k
R82: library part CMP-0025917-5, "RES, 39 k, 5%, 0.1 W, 0603", Manufacturer=Yageo, Power_W=100mW, Supplier Part Number 1=311-39KGRCT-ND, TempCo="100 ppm/C", Tolerance_%=5%, Value2=0.1W, Value_Code=39k0, ValueDisplayed=39k
R83 R84: library part CMP-0018664-3, "RES, 390 k, 5%, 0.25 W, AEC-Q200 Grade 0, 1206", Manufacturer=Vishay-Dale, Power_W=250mW, Supplier Part Number 1=541-390KECT-ND, TempCo="200 ppm/C", Tolerance_%=5%, Value2=0.25W, Value_Code=390k
RT1 RT2 RT3: library part CMP-0002556-2, "Thermistor NTC, 4.70 ohm, 20%, 8.5mm Disc", Manufacturer=TDK, Power_W=1.4W, Supplier Part Number 1=B57153S479M51-ND, Tolerance_%=20%
T1: library part CMP-0094994-1, "TRANSFORMER", Frequency_Fixed=40kHz, Manufacturer=Wurth, Operating Temperature Range="-40°C to +125°C", Voltage_Isolation_Vrms=500V
TP1 TP2 TP3 TP5: library part CMP-0055149-2, "Test Point, Multipurpose, White, TH", Color=White, Manufacturer="Keystone Electronics", Supplier Part Number 1=36-5012-ND
TP4: library part CMP-0055147-2, "Test Point, Multipurpose, Red, TH", Color=Red, Manufacturer="Keystone Electronics", Supplier Part Number 1=36-5010-ND
TP6: library part CMP-0055137-2, "Test Point, Miniature, Red, TH", Color=Red, Manufacturer="Keystone Electronics", Supplier Part Number 1=36-5000-ND
TP7 TP10 TP12 TP13 TP14 TP15 TP16 TP18 TP21: library part CMP-0055140-2, "Test Point, Miniature, Orange, TH", Color=Orange, Manufacturer="Keystone Electronics", Supplier Part Number 1=36-5003-ND
TP8 TP22: library part CMP-0055148-2, "Test Point, Multipurpose, Black, TH", Color=Black, Manufacturer="Keystone Electronics", Supplier Part Number 1=36-5011-ND
TP9: library part CMP-0055138-2, "Test Point, Miniature, Black, TH", Color=Black, Manufacturer="Keystone Electronics", Supplier Part Number 1=36-5001-ND
TP11: library part CMP-0003825-1, "1mm Test Point, SMT", Manufacturer=Any
U1: library part CMP-0013050-3, "High-Frequency Multi-Mode Synchronous Rectifier Controller, DBV0005A (SOT-23-5)", Alternate Manufacturer="Texas Instruments", Alternate PartNumber=UCC24612-1DBVT
U2: library part CMP-0006181-3, "Optocoupler, 5 kV, 80-160% CTR, SMT", Manufacturer="Fairchild Semiconductor", PartNumber=FOD817ASD, Supplier Part Number 1=FOD817ASDCT-ND, Voltage_Isolation_Vrms=5kV
U3: library part CMP-0078369-2, "High-Efficiency Low-Cost Flyback Controller with Secondary-Side Regulation, DBV0006A (SOT-23-6)", Alternate Manufacturer="Texas Instruments"
U4: library part CMP-0033091-1, "Adjustable Precision Shunt Regulator, 34 ppm / degC, 100 mA, -40 to 85 degC, 3-pin SOT-23 (DBZ), Green (RoHS & no Sb/Br)", Manufacturer="Texas Instruments", Rating=Catalog, Temp Coeff(Max)(ppm/ degree C)=92, Temp Coeff(Typ)(ppm/ degree C)=34
U5: library part CMP-0032057-1, "Single Supply Voltage Supervisor for 5 V Systems with Programmable Time Delay, 1 Supply Monitored, -40 to 85 degC, 8-pin SOIC (D), Green (RoHS & no Sb/Br)", Manufacturer="Texas Instruments", Rating=Catalog, Threshold Voltage 1 (typ)(Typ)(V)=4.55
U6: library part CMP-0124349-2, "V-Ref Adjustable/Precision 2.5V to 36V 100mA 3-Pin SOT-23 T/R", Digikey Part Number=296-47201-1-ND, Manufacturer="Texas Instruments", Max Supply Voltage=36V, Min Supply Voltage=2.5V, Mouser Part Number=595-ATL431AQDBZR, Operating Temperature Range="-40°C to +125°C", Output Voltage=2.5-36V
U7: library part CMP-0067160-2, "Integrated 5-A 24-V Wide Input Range Boost/SEPIC/Flyback DC-DC Regulator, RTE0016C (WQFN-16)", Alternate Manufacturer="Texas Instruments", Alternate PartNumber=TPS55330RTET
U8: library part CMP-0090278-3, "18V, 1A H-bridge motor driver, PWM, PH/EN, ½ bridge control, with low power sleep mode", Manufacturer="Texas Instruments", Max Supply Voltage=18V, Min Supply Voltage=4.5V, Operating Temperature Range="-40°C to +150°C", Switching Frequency=100kHz
U9: library part CMP-0051576-2, "Low-Power Single 2-Input Positive-AND Gate, DBV0005A (SOT-23-5)", F @ Nom Voltage(Max)(Mhz)=100, Generic Part Number=SN74AUP1G08, ICC @ Nom Voltage(Max)(mA)=0.0009, Manufacturer="Texas Instruments", Operating Temperature Range="-40 to 85 C", Rating=Catalog, tpd @ Nom Voltage(Max)(ns)=32.8,20.9,14.2,11,7.6,6.2, Voltage(Nom)(V)=0.8,1.2,1.5,1.8,2.5,3.3
U10 U12 U13 U15: library part CMP-0120116-1, "±24 V Low Capacitance Surge Diode for Industrial Networks in SOT-23 Package", Breakdown Voltage=25.5V, Clamping Voltage=35V, Digikey Part Number=296-TSM24CADBZRCT-ND, Manufacturer="Texas Instruments", Mouser Part Number=595-TSM24CADBZR, Operating Temperature Range="-55°C to +150°C", ValueDisplayed=14pF
U11: library part CMP-0085889-2, "Small-Size Micropower Low-Voltage Comparator, DCK0005A (SOT-SC70-5)", Alternate Manufacturer="Texas Instruments", Alternate PartNumber=TLV7021DCKT, Operating Temperature Range="-40 to 125 C", Rating=Catalog
U14: library part CMP-0032940-1, "Adjustable Precision Shunt Regulator, 34 ppm / degC, 100 mA, -40 to 125 degC, 5-pin SOT-23 (DBV), Green (RoHS & no Sb/Br)", Manufacturer="Texas Instruments", Rating=Catalog, Temp Coeff(Max)(ppm/ degree C)=92, Temp Coeff(Typ)(ppm/ degree C)=34
U16 U17 U18 U19: library part CMP-0121043-1, Manufacturer="Texas Instruments", Operating Temperature Range=to
U20: library part CMP-0006177-3, "Optocoupler, 5 kV, 80-160% CTR, SMT", Manufacturer="Fairchild Semiconductor", Supplier Part Number 1=FOD817AS-ND, Voltage_Isolation_Vrms=5kV
ZZ1: library part CMP-0003616-3
ZZ2: library part CMP-0077236-1
ZZ3: library part CMP-0077237-1
ZZ4: library part CMP-0077238-1

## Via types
v1: diameter 0.635, hole 0.305, Top Layer to Bottom Layer, tented both sides, 118 vias
v2: diameter 1.27, hole 0.635, Top Layer to Bottom Layer, tented both sides, 35 vias
v3: diameter 0.762, hole 0.406, Top Layer to Bottom Layer, tented both sides, 4 vias
v4: diameter 0.559, hole 0.254, Top Layer to Bottom Layer, tented both sides, 4 vias
v5: diameter 0.864, hole 0.406, Top Layer to Bottom Layer, tented both sides, 3 vias

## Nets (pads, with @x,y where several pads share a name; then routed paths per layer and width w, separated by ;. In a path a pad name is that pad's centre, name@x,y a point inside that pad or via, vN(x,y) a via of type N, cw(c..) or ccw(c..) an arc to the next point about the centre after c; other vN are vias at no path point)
3V3: C61.1 J9.6 R39.2 R57.1 R63.2 R69.2 R78.2 R85.2 R92.2 U9.5 | length 253.9
  Top Layer w0.254: R78.2@126.831,86.5 R78.2@126.86,86.529
  Top Layer w0.635: R57.1@75.222,96 v2(76.922,96) ; R63.2@86.476,87.6 86.411,87.6 86.122,87.89 86.122,88.878 v2(86,89) 87.128,89 87.408,89.28 87.408,90.517 U9.5@87.411,90.52 ; R92.2@92.434,88.685 92.434,88.71 92.591,88.867 92.616,88.867 92.628,88.878 93.878,88.878 v2(94,89) ; v2(125.25,86.5) 125.264,86.514 126.817,86.514 R78.2@126.831,86.5 ; R85.2@141.713,79.379 141.713,79.444 141.73,79.461 141.961,79.461 v2(143,80.5) 142.879,80.621 142.879,80.817 142.689,81.006 141.87,81.006 141.713,81.164 R69.2@141.713,81.189
  Inside 2 w1.27: v2(57,88.5) 69.422,88.5 v2(76.922,96) 79,96 v2(86,89) 124.5,89 125.25,88.25 v2(125.25,86.5) ; J9.6@116.08,4.73 116.153,4.657 116.153,3.811 117.424,2.54 140.04,2.54 154.25,16.75 154.25,80.25 148,86.5 v2(125.25,86.5) ; v2(143,80.5) 142.42,81.08 127.42,81.08 125.25,83.25 v2(125.25,86.5)
  Bottom Layer w0.635: R39.2@56.31,90.196 56.468,90.039 56.468,89.204 57,88.672 v2(57,88.5)
5V: C64.1 J9.5 U11.5 | length 125
  Top Layer w0.254: C64.1@134.713,82.829 134.863,82.979 134.863,84.436 U11.5@134.868,84.441
  Top Layer w0.635: v2(133,83.25) 133.172,83.25 133.411,83.011 134.555,83.011 134.713,82.854 C64.1@134.713,82.829
  Inside 2 w1.27: J9.5@116.08,7.27 116.153,7.343 116.153,9.653 117.25,10.75 142.75,10.75 151.5,19.5 151.5,78.75 147,83.25 v2(133,83.25)
12V: C18.1 C25.1 C26.1 D11.2 F4.2 L7.2 R14.1 R18.2 R20.2 R22.2 R31.1 TP4.1 TP6.1 U1.4 | length 187.8
  Top Layer w0.381: TP6.1@102.003,24.12 102.003,28.53 104.283,30.81 R31.1@106.993,30.81
  Top Layer w0.508: D11.2@106.983,32.44 106.988,32.435 v3(106.988,31.625) 106.988,30.815 R31.1@106.993,30.81
  Top Layer w0.635: TP4.1@125.984,24.384 125.984,24.81 126.784,25.61 R20.2@126.784,27.432
  Top Layer w1.27: F4.2@61.572,89.693 61.572,83.428 66.25,78.75 89.5,78.75 93.98,74.27 93.98,39.353 96.673,36.66 101.137,36.66 108.467,43.99 C25.1@112.233,43.99
  Inside 2 w1.27: TP6.1@101.858,23.974 TP6.1@102.003,24.12 102.003,22.197 103,21.2 122.8,21.2 TP4.1@125.984,24.384 127.5,25.9 127.5,40.933 C26.1@124.446,43.988
  Bottom Layer w0.381: R22.2@101.657,26.56 101.83,26.387 101.83,24.293 TP6.1@102.003,24.12
  Bottom Layer w0.508: v3(106.988,31.625) 106.988,31.631 107.793,32.436 C18.1@107.793,35.22 107.798,35.225 107.798,36.605 U1.4@107.803,36.61
  Bottom Layer w1.5: C25.1@112.233,43.99 112.235,43.989 116.1,43.989 119.75,43.989 C26.1@124.446,43.988 C26.1@124.446,43.988 124.447,43.987 127.611,43.987 R14.1@127.612,43.985
+12V: C43.1 D18.1 J9.1 J9.2 L9.2 R14.2 U5.2 U5.8 | length 78.3
  Top Layer w0.508: L9.2@122.653,66.67 122.653,66.395 123.049,65.999 123.988,65.999 v1(123.997,65.99)
  Top Layer w1.27: L9.2@122.653,66.67 L9.2@122.653,66.945
  Inside 2 w0.508: v1(120.228,60.27) 123.997,64.039 v1(123.997,65.99)
  Bottom Layer w0.508: D18.1@118.293,58.661 118.299,58.655 U5.8@120.29,58.655 ; v1(120.228,60.27) 120.253,60.246 120.253,58.693 U5.8@120.29,58.655 ; R14.2@130.512,43.985 130.512,53.926 127.653,56.785 C43.1@127.653,56.81 127.653,56.835 127.108,57.38 U5.2@125.783,57.38 123.823,57.38 122.553,58.65 U5.8@120.333,58.65 120.295,58.65 U5.8@120.29,58.655
  Bottom Layer w1.5: J9.2@121.16,4.73 J9.1@121.16,7.27 121.16,9.66 130.512,19.012 R14.2@130.512,43.985
+14V_OUT: D2.1 J9.3 | length 65.2
  Bottom Layer w0.508: D2.1@114.903,57.526 114.903,56.426 116.698,54.632 116.698,50.052 118.75,48 118.75,47 120.117,45.633 128.367,45.633 129,45 129,31.25 118.62,20.87 J9.3@118.62,7.27
+14V_SW: D1.2 D14.2 D16.2 R1.1 T1.14 | length 2.1
  Top Layer w0.381: v1(101,62.637) 101.454,63.09 D14.2@102.913,63.09
-14V_OUT: D6.2 J9.4 | length 55.2
  Bottom Layer w0.508: D6.2@114.903,53.14 115.056,53.14 115.259,52.936 115.259,52.784 115.958,52.085 115.958,48.958 113.946,46.946 112.446,46.946 110.75,45.25 110.75,27.5 117.349,20.901 117.349,6.001 J9.4@118.62,4.73
AGND2: C47.1 C51.2 C52.2 C53.1 NT1.1 R54.1 R55.1 R56.1 U7.5 U7.6
  other v1: 129.75,47.25 131.25,47.25 129.069,57.39
Fly_ON: C36.1 D15.1 Q3.1@109.503,69.06 Q6.1@124.605,51.646 R21.2 R38.2 | length 49.2
  Top Layer w0.254: D15.1@107.673,68.66 108.417,68.66 108.817,69.06 Q3.1@109.503,69.06
  Top Layer w0.381: R21.2@103.327,65.1 103.183,65.244 C36.1@103.183,68.67 103.183,69.737 v1(103.295,69.848) 104.037,70.59 106.736,70.59 107.673,69.653 D15.1@107.673,68.66
  Inside 2 w0.381: v1(103.295,69.848) 103.295,59.548 107.463,55.38 111.873,55.38 115.253,52 117.924,52 v1(119.915,50.009)
  Bottom Layer w0.381: v1(119.915,50.009) 120.745,50.009 122.382,51.646 Q6.1@124.605,51.646
Fly_ON_EXT: J9.16 Q3.3@109.503,68.06 | length 129.5
  Top Layer w0.254: Q3.3@109.503,68.06 112.836,68.06 v3(113.846,67.05)
  Inside 2 w0.254: J9.16@103.38,4.755 102.116,6.02 102.116,10.116 108,16 138,16 143,21 143,64 139.95,67.05 v3(113.846,67.05)
GND: C2.2 C6.2 C7.2 C16.2 C17.2 C30.2 C32.2 C33.2 C35.1 D13.1 L5.3 R32.1 R35.1 R37.1 T1.7 U3.5 | length 22.4
  Top Layer w0.508: U3.5@61.882,50.234 U3.5@61.928,50.28
  Bottom Layer w0.508: D13.1@59.203,36.12 59.203,38.63 v1(59.343,38.77) v1(60.123,38.77)
  Bottom Layer w1.27: C30.2@74.028,35.215 72.218,35.215 71.373,36.06 T1.7@71.373,40.41 74.44,40.41 75.551,41.521 C7.2@75.551,44.044 C6.2@79.891,44.044
  other v1: 60.963,38.76 63.303,50.28
LINE1_IN: C54.1 C75.2 F1.2 J1.1 K1.6 TP1.1 | length 141.9
  Top Layer w1.27: 15.735,81.344 15.841,81.45 v5(40.964,81.45)
  Top Layer w2.54: C54.1@8.484,101.918 15.723,101.918 15.735,101.93 ; TP1.1@15.813,63.54 15.735,63.618 15.735,81.344 15.735,101.93 ; J1.1@27.422,157.43 20.922,157.43 15.735,152.243 15.735,101.93
  Bottom Layer w1.27: v5(40.964,81.45) C75.2@40.964,83.434
  Bottom Layer w2.54: F1.2@15.813,58.735 TP1.1@15.813,63.54
LINE1_OUT: C62.1 J2.1 K1.5 R87.2 | length 73.2
  Bottom Layer w1.27: J2.1@132.322,156.99 147.542,156.99 150.036,154.496 150.036,105.474 C62.1@150.036,100.08
LINE2_IN: C55.1 F2.2 J3.1 K1.7 TP2.1 | length 123.1
  Inside 1 w2.54: C55.1@8.484,90.234 11.606,90.234 ; TP2.1@15.813,43.93 11.925,47.818 11.925,140.82 14.595,143.49 J3.1@27.422,143.49
  Bottom Layer w2.54: F2.2@15.783,39.04 15.813,39.07 TP2.1@15.813,43.93
LINE2_OUT: C65.1 J4.1 K1.4 R88.2 | length 66.3
  Inside 2 w1.27: J4.1@132.322,143.49 143.77,143.49 146.5,140.76 146.5,105.828 143.922,103.25 141,103.25 138.875,101.125 138.875,100.095 C65.1@138.86,100.08
  Bottom Layer w1.27: R88.2@138.832,105.474 138.832,105.199 138.86,105.171 C65.1@138.86,100.08
LINE3_IN: C56.1 F3.2 J5.1 K1.8 TP3.1 | length 129
  Inside 2 w2.54: C56.1@8.558,78.55 11.606,78.55 ; TP3.1@15.813,24.32 11.835,28.298 11.835,126.66 15.165,129.99 J5.1@27.422,129.99
  Bottom Layer w2.54: F3.2@15.783,19.345 15.813,19.375 TP3.1@15.813,24.32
